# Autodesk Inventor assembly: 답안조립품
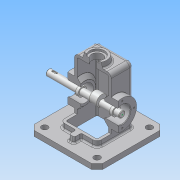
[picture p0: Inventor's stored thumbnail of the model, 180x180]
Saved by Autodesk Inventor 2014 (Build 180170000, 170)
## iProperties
Created: 2016-02
Part Number: 답안조립품
Document SubType Name: Assembly
Designer: User
Author: User
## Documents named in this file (3)
- C:\Documents and Settings\User\바탕 화면\460211V1013\답안조립품.iam
- C:\Documents and Settings\User\바탕 화면\460211V1013\본체.ipt
- C:\Documents and Settings\User\바탕 화면\460211V1013\편심축.ipt
